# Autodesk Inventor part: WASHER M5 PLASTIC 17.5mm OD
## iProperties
Created: 2007-06
Part Number: WASHER M5 PLASTIC 17.5mm OD
Material: UHMW, White
Document SubType Name: Modeling
Designer: Andy Moles
Mass: 0.405888 g
Surface Area: 5.76938 cm^2
Volume: 0.431796 cm^3
Density: 0.94 g/cm^3
Author: Andy Moles
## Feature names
1. Extrusion1
